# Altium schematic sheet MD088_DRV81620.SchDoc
size 431 x 279 mm; Date: Not shown in title block; ApprovedBy: Not shown in title block; CheckedBy: Not shown in title block; Author: Not shown in title block; CompanyName: Not shown in title block; Engineer: Not shown in title block; Organization: Not shown in title block; Address1: Not shown in title block; Address2: Not shown in title block; Address3: Not shown in title block; Address4: Not shown in title block; DocumentNumber: 1; Revision: Use project parameter SCH_Rev; SheetNumber: 1; SheetTotal: 4; PageSetup: Record=PageOptions¦CenterHorizontal=True¦CenterVertical=True¦PrintScale=1.00¦XCorrection=1.00¦YCorrection=1.00¦PrintKind=0¦BorderSize=5000000¦LeftOffset=0¦BottomOffset=0¦Orientation=2¦PaperLength=1000¦PaperWidth=1000¦Scale=100¦PaperSource=15¦PrintQuality=600¦MediaType=1¦DitherType=10¦PaperKind=Letter¦PrintScaleMode=1
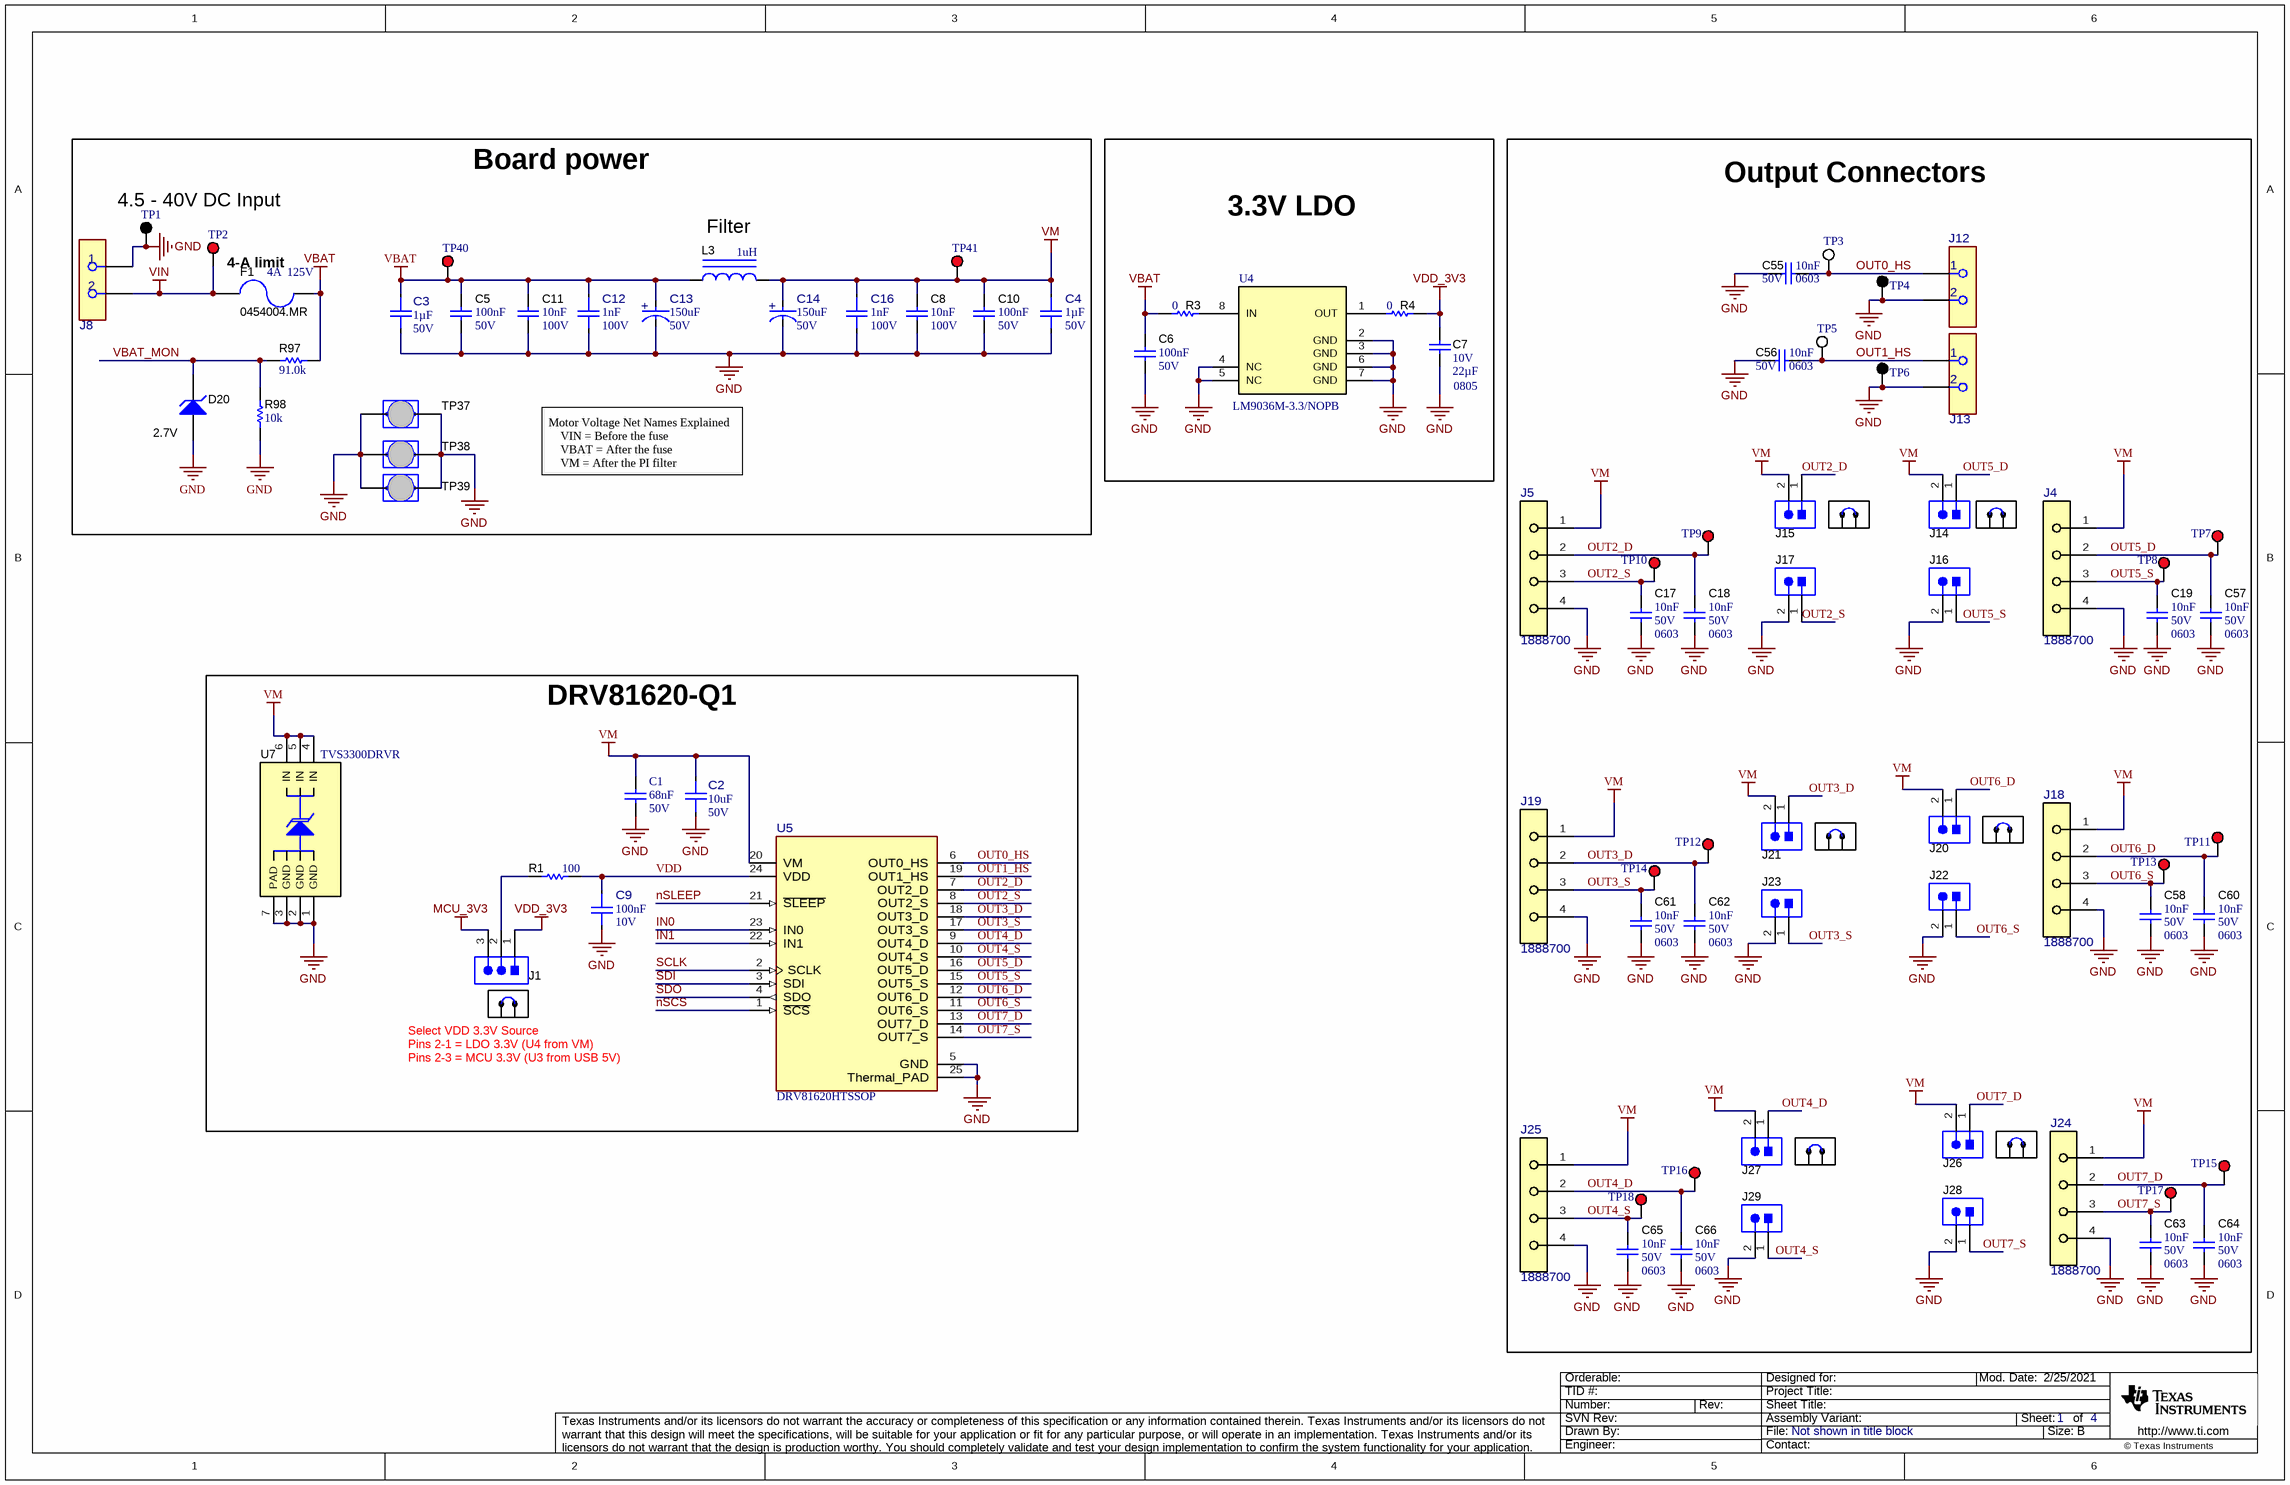
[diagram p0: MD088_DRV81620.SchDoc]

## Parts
C1  Cap_F: 68nF  Rated Voltage (DC): 50V  [WCAP-CSGP_0603_L1.6W0.8H0.8_Reflow]  (hidden comment: 885012206094)
C2  ValueDisplayed: 10uF  VDC_V: 50V  [FP-885012209073_1210-MFG]  (hidden comment: 885012209073)
C3  Cap_F: 1µF  VDC_V: 50V  [FP-885012206126_0603-MFG]  (hidden comment: 885012206126)
C4  Cap_F: 1µF  VDC_V: 50V  [FP-885012206126_0603-MFG]  (hidden comment: 885012206126)
C5  Cap_F: 100nF  VDC_V: 50V  [0603]  (hidden comment: 885012206095)
C6  Cap_F: 100nF  VDC_V: 50V  [0603]  (hidden comment: 885012206095)
C7  PackageReference: 0805  VDC_V: 10V  ValueDisplayed: 22µF  [0805_150]  (hidden comment: 885012107011)
C8  Value2: 100V  Cap_F: 10nF  [0603]  (hidden comment: 885012206114)
C9  value 100nF  VDC_V: 10V  [FP-885012205018_0402-MFG]  (hidden comment: 885012205018)
C10  Cap_F: 100nF  VDC_V: 50V  [0603]  (hidden comment: 885012206095)
C11  Value2: 100V  Cap_F: 10nF  [0603]  (hidden comment: 885012206114)
C12  ValueDisplayed: 1nF  VDC_V: 100V  [FP-885012006085_0603-MFG]  (hidden comment: 885012006085)
C13  VDC_V: 50V  ValueDisplayed: 150uF  [FP-865080657017_RADIAL-MFG]  (hidden comment: 865080657017)
C14  VDC_V: 50V  ValueDisplayed: 150uF  [FP-865080657017_RADIAL-MFG]  (hidden comment: 865080657017)
C16  ValueDisplayed: 1nF  VDC_V: 100V  [FP-885012006085_0603-MFG]  (hidden comment: 885012006085)
C17  VDC_V: 50V  Cap_F: 10nF  [0603]  (hidden comment: 885012206089)
C18  VDC_V: 50V  Cap_F: 10nF  [0603]  (hidden comment: 885012206089)
C19  VDC_V: 50V  Cap_F: 10nF  [0603]  (hidden comment: 885012206089)
C55  VDC_V: 50V  Cap_F: 10nF  [0603]  (hidden comment: 885012206089)
C56  VDC_V: 50V  Cap_F: 10nF  [0603]  (hidden comment: 885012206089)
C57  VDC_V: 50V  Cap_F: 10nF  [0603]  (hidden comment: 885012206089)
C58  VDC_V: 50V  Cap_F: 10nF  [0603]  (hidden comment: 885012206089)
C60  VDC_V: 50V  Cap_F: 10nF  [0603]  (hidden comment: 885012206089)
C61  VDC_V: 50V  Cap_F: 10nF  [0603]  (hidden comment: 885012206089)
C62  VDC_V: 50V  Cap_F: 10nF  [0603]  (hidden comment: 885012206089)
C63  VDC_V: 50V  Cap_F: 10nF  [0603]  (hidden comment: 885012206089)
C64  VDC_V: 50V  Cap_F: 10nF  [0603]  (hidden comment: 885012206089)
C65  VDC_V: 50V  Cap_F: 10nF  [0603]  (hidden comment: 885012206089)
C66  VDC_V: 50V  Cap_F: 10nF  [0603]  (hidden comment: 885012206089)
D20  value 2.7V  [SOD-123]  (hidden comment: MMSZ4682-E3-08)
F1  0454004.MR  Irating_A: 4A  VDC_V: 125V  [SloBlo452]
J1  61300311121  [WURTH_61300311121]  (value not drawn)
J4  1888700  [FP-1888700_HDR4-MFG]
J5  1888700  [FP-1888700_HDR4-MFG]
J8  691250610002  [FP-691250610002_CONN_TERM_BLOCK2-MFG]  (value not drawn)
J12  691101710002  [FP-691101710002_TERM_BLK_2-MFG]  (value not drawn)
J13  691101710002  [FP-691101710002_TERM_BLK_2-MFG]  (value not drawn)
J14  HTSW-102-07-G-S  [Samtec_HTSW-102-07-G-S]  (value not drawn)
J15  HTSW-102-07-G-S  [Samtec_HTSW-102-07-G-S]  (value not drawn)
J16  HTSW-102-07-G-S  [Samtec_HTSW-102-07-G-S]  (value not drawn)
J17  HTSW-102-07-G-S  [Samtec_HTSW-102-07-G-S]  (value not drawn)
J18  1888700  [FP-1888700_HDR4-MFG]
J19  1888700  [FP-1888700_HDR4-MFG]
J20  HTSW-102-07-G-S  [Samtec_HTSW-102-07-G-S]  (value not drawn)
J21  HTSW-102-07-G-S  [Samtec_HTSW-102-07-G-S]  (value not drawn)
J22  HTSW-102-07-G-S  [Samtec_HTSW-102-07-G-S]  (value not drawn)
J23  HTSW-102-07-G-S  [Samtec_HTSW-102-07-G-S]  (value not drawn)
J24  1888700  [FP-1888700_HDR4-MFG]
J25  1888700  [FP-1888700_HDR4-MFG]
J26  HTSW-102-07-G-S  [Samtec_HTSW-102-07-G-S]  (value not drawn)
J27  HTSW-102-07-G-S  [Samtec_HTSW-102-07-G-S]  (value not drawn)
J28  HTSW-102-07-G-S  [Samtec_HTSW-102-07-G-S]  (value not drawn)
J29  HTSW-102-07-G-S  [Samtec_HTSW-102-07-G-S]  (value not drawn)
L3  ValueDisplayed: 1uH  [WE-HCC_1210]  (hidden comment: 7443320100)
R1  ValueDisplayed: 100  [0402S]  (hidden comment: RC0402FR-07100RL)
R3  value 0  [0603L]  (hidden comment: Resistor)
R4  value 0  [0603L]  (hidden comment: Resistor)
R97  ValueDisplayed: 91.0k  [0603L]  (hidden comment: RG1608P-913-B-T5)
R98  ValueDisplayed: 10k  [0603L]  (hidden comment: RC0603JR-0710KL)
SH-J1  60900213421  [Wurth_60900213421]  (value not drawn)
SH-J23  60900213421  [Wurth_60900213421]  (value not drawn)
SH-J24  60900213421  [Wurth_60900213421]  (value not drawn)
SH-J25  60900213421  [Wurth_60900213421]  (value not drawn)
SH-J26  60900213421  [Wurth_60900213421]  (value not drawn)
SH-J29  60900213421  [Wurth_60900213421]  (value not drawn)
SH-J34  60900213421  [Wurth_60900213421]  (value not drawn)
TP1  5011  [Keystone5011]  (value not drawn)
TP2  5010  [Keystone5010]  (value not drawn)
TP3  5012  [Keystone5012]  (value not drawn)
TP4  5011  [Keystone5011]  (value not drawn)
TP5  5012  [Keystone5012]  (value not drawn)
TP6  5011  [Keystone5011]  (value not drawn)
TP7  5010  [Keystone5010]  (value not drawn)
TP8  5010  [Keystone5010]  (value not drawn)
TP9  5010  [Keystone5010]  (value not drawn)
TP10  5010  [Keystone5010]  (value not drawn)
TP11  5010  [Keystone5010]  (value not drawn)
TP12  5010  [Keystone5010]  (value not drawn)
TP13  5010  [Keystone5010]  (value not drawn)
TP14  5010  [Keystone5010]  (value not drawn)
TP15  5010  [Keystone5010]  (value not drawn)
TP16  5010  [Keystone5010]  (value not drawn)
TP17  5010  [Keystone5010]  (value not drawn)
TP18  5010  [Keystone5010]  (value not drawn)
TP37  Jumper_2p  [Harwin_D3082-05]  (value not drawn)
TP38  Jumper_2p  [Harwin_D3082-05]  (value not drawn)
TP39  Jumper_2p  [Harwin_D3082-05]  (value not drawn)
TP40  5010  [Keystone5010]  (value not drawn)
TP41  5010  [Keystone5010]  (value not drawn)
U4  LM9036M-3.3/NOPB  [D0008A_N]
U5  DRV81620HTSSOP  [PWP0024T-MFG]
U7  TVS3300DRVR  [DRV0006A]

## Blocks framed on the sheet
Board power: C3-C5 C8 C10-C14 C16 D20 F1 J8 L3 R97 R98 TP1 TP2 TP37-TP41
3.3V LDO: C6 C7 R3 R4 U4
Output Connectors: C17-C19 C55-C58 C60-C66 J4 J5 J12-J29 SH-J1 SH-J23-SH-J26 SH-J29 TP3-TP18
DRV81620-Q1: C1 C2 C9 J1 R1 SH-J34 U5 U7

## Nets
GND: C1.1 C2.1 C3.2 C4.2 C5.2 C6.2 C7.2 C8.1 C9.2 C10.2 C11.1 C12.2 C13.1(CATHODE) C14.1(CATHODE) C16.2 C17.2 C18.2 C19.2 C55.1 C56.1 C57.2 C58.2 C60.2 C61.2 C62.2 C63.2 C64.2 C65.2 C66.2 D20.2(A) J4.4 J5.4 J8.1 J12.2 J13.2 J16.2 J17.2 J18.4 J19.4 J22.2 J23.2 J24.4 J25.4 J28.2 J29.2 R98.2 TP1.1 TP4.1 TP6.1 TP37.1 TP37.2 TP38.1 TP38.2 TP39.1 TP39.2 U4.2(GND) U4.3(GND) U4.4(NC) U4.5(NC) U4.6(GND) U4.7(GND) U5.5(GND) U5.25(Thermal_PAD) U7.1(GND) U7.2(GND) U7.3(GND) U7.7(PAD)
MCU_3V3: J1.3
VBAT: C3.1 C5.1 C6.1 C11.2 C12.1 C13.2(ANODE) F1.1 L3.1 R3.2 R97.2 TP40.1
VDD_3V3: C7.1 J1.1 R4.1
VIN: F1.2 J8.2 TP2.1
VM: C1.2 C2.2 C4.1 C8.2 C10.1 C14.2(ANODE) C16.1 J4.1 J5.1 J14.2 J15.2 J18.1 J19.1 J20.2 J21.2 J24.1 J25.1 J26.2 J27.2 L3.2 TP41.1 U5.20(VM) U7.4(IN) U7.5(IN) U7.6(IN)
IN0: U5.23(IN0)
IN1: U5.22(IN1)
nSCS: U5.1(~{SCS})
nSLEEP: U5.21(~{SLEEP})
OUT0_HS: C55.2 J12.1 TP3.1 U5.6(OUT0_HS)
OUT1_HS: C56.2 J13.1 TP5.1 U5.19(OUT1_HS)
OUT2_D: C18.1 J5.2 J15.1 TP9.1 U5.7(OUT2_D)
OUT2_S: C17.1 J5.3 J17.1 TP10.1 U5.8(OUT2_S)
OUT3_D: C62.1 J19.2 J21.1 TP12.1 U5.18(OUT3_D)
OUT3_S: C61.1 J19.3 J23.1 TP14.1 U5.17(OUT3_S)
OUT4_D: C66.1 J25.2 J27.1 TP16.1 U5.9(OUT4_D)
OUT4_S: C65.1 J25.3 J29.1 TP18.1 U5.10(OUT4_S)
OUT5_D: C57.1 J4.2 J14.1 TP7.1 U5.16(OUT5_D)
OUT5_S: C19.1 J4.3 J16.1 TP8.1 U5.15(OUT5_S)
OUT6_D: C60.1 J18.2 J20.1 TP11.1 U5.12(OUT6_D)
OUT6_S: C58.1 J18.3 J22.1 TP13.1 U5.11(OUT6_S)
OUT7_D: C64.1 J24.2 J26.1 TP15.1 U5.13(OUT7_D)
OUT7_S: C63.1 J24.3 J28.1 TP17.1 U5.14(OUT7_S)
SCLK: U5.2(SCLK)
SDI: U5.3(SDI)
SDO: U5.4(SDO)
VBAT_MON: D20.1(K) R97.1 R98.1
VDD: C9.1 R1.1 U5.24(VDD)
NetJ1_2: J1.2 R1.2
NetR3_1: R3.1 U4.8(IN)
NetR4_2: R4.2 U4.1(OUT)

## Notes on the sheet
- (near TP1) 4.5 - 40V DC Input
- (near L3) Filter
- 4-A limit
- Motor Voltage Net Names Explained
  VIN = Before the fuse
  VBAT = After the fuse
  VM = After the PI filter
- (near SH-J34) Select VDD 3.3V Source
- (near SH-J34) Pins 2-3 = MCU 3.3V (U3 from USB 5V)
- (near SH-J34) Pins 2-1 = LDO 3.3V (U4 from VM)

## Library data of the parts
C1 = CMP-0111903-1: 68 nF ±10% 50V Ceramic Capacitor X7R 0603; Manufacturer: Wurth Elektronik; Capacitance Tolerance: +/-10%; Dissipation Factor: 3%; Insulation Resistance: 7.4GOhm; Match Code: WCAP-CSGP; Technical Reference: X7R0603683K050DFCT10000; Value: 68nF
C2 = CMP-0097489-1: 10 µF ±10% 50V Ceramic Capacitor X7R 1210 (3225 Metric); Manufacturer: Wurth Electronics; SizeZ_mm: 2.8mm; AEC Qualified: No; Value: 10µF; TempCo: 15%
C3 C4 = CMP-0120896-1: 1 µF ±10% 50V Ceramic Capacitor X7R 0603 (1608 Metric); Manufacturer: Wurth Electronics; AEC Qualified: No; SizeZ_mm: 0.95mm; TempCo: 15%; ValueDisplayed: 1uF; Value: 1µF
C5 C6 C10 = CMP-0006837-4: CAP, CERM, 0.1 uF, 50 V, +/- 10%, X7R, 0603; Manufacturer: Wurth Elektronik; TaMin_C: -55°C; Polarized: N; SizeAreaWB_mm2: 4.68; Value1: Unknown; U/M: EA; Value: 0.1uF; TaMax_C: 125°C; SizeZ_mm: 1; SizeX_mm: 1.6; SizeY_mm: 0.8; SizeArea_mm2: 1.28; AEC Category: Q200
C7 = CMP-0078153-1: CAP, CERM, 22 µF, 10 V,+/- 20%, X5R, 0805; Manufacturer: Wurth Elektronik; TaMin_C: -55°C; Polarized: N; SizeAreaWB_mm2: 6.75; U/M: EA; Value: 22uF; TaMax_C: 85°C; SizeZ_mm: 1.5; SizeX_mm: 2; SizeY_mm: 1.25; SizeArea_mm2: 2.5; AEC Category: Q200
C8 C11 = CMP-0079993-1: CAP, CERM, 0.01 µF, 100 V,+/- 10%, X7R, 0603; Manufacturer: Wurth Elektronik; TaMin_C: -55°C; Polarized: N; SizeAreaWB_mm2: 4.68; U/M: EA; Value: 0.01uF; TaMax_C: 105°C; SizeZ_mm: 1; SizeX_mm: 1.6; SizeY_mm: 0.8; SizeArea_mm2: 1.28; AEC Category: Q200; ValueDisplayed: 0.01µF
C9 = CMP-0090362-1: 0.1µF ±10% 10V Ceramic Capacitor X7R 0402 (1005 Metric); Manufacturer: Wurth Electronics; AEC Qualified: No; SizeZ_mm: 0.55mm; ValueDisplayed: 100000pF; TempCo: 15%
C12 C16 = CMP-0097311-1: 1000 pF ±5% 100V Ceramic Capacitor C0G, NP0 0603 (1608 Metric); Manufacturer: Wurth Electronics; TempCo: 30ppm/°C; SizeZ_mm: 0.87mm; AEC Qualified: No; Value: 1nF
C13 C14 = CMP-0097488-1: 150 µF 50 V Aluminum Electrolytic Capacitors Radial, Can - SMD 2000 Hrs @ 105°C; Manufacturer: Wurth Electronics; Cap_F: 150µF; Life: 2000Hours; IRMS_A: 600mA; Dissipation Factor: 12%; Value: 150µF; Leakage Current: 75uA; Tolerance_%: 20%; AEC Qualified: No; SizeZ_mm: 10.5mm
C17-C19 C55-C58 C60-C66 = CMP-0750039-1: CAP, CERM, 0.01 µF, 50 V,+/- 10%, X7R, 0603; Manufacturer: Wurth Elektronik; Polarized: N; AEC Category: Q200; TaMax_C: 125°C; SizeAreaWB_mm2: 4.68; Value: 0.01uF; SizeArea_mm2: 1.28; SizeY_mm: 0.8; SizeZ_mm: 1; ValueDisplayed: 0.01µF; SizeX_mm: 1.6; U/M: EA; TaMin_C: -55°C
D20 = CMP-0077592-3: Diode, Zener, 2.7 V, 500 mW, SOD-123; Manufacturer: Vishay-Semiconductor; AEC Category: Q101; AEC Qualified: N; SizeAreaWB_mm2: 13.095; SizeY_mm: 1.7; SizeX_mm: 3.85; Value1: 0.5W; SizeArea_mm2: 6.545; SizeZ_mm: 1.35; RJA_CperW: 340; Power_W: 500mW
F1 = CMP-0003486-2: Fuse, 4 A, 125VAC/VDC, SMD; Manufacturer: Littelfuse; MeltingTyp: 34.4; Rtyp_Ohm: 0.0186; Interrupt_AC: 50A; Value: 4A / 125V
J1 = CMP-0054796-4: Header, 2.54 mm, 3x1, Gold, TH; Manufacturer: Wurth Elektronik; Green_Lifecycle: Active; Green_REACh: Passed; CT: FALSE; CNHeader: TRUE
J4 J5 J18 J19 J24 J25 = CMP-0086377-1: Conn; Term Blk; PCB; Screw; 4; 5.08 mm; Front; 24-14 AWG; 16 A; 250 V; Solder; Manufacturer: Phoenix Contact; ContactFinish: Tin; Current_A: 16A; Row_Count: 1; Voltage_V: 400V
J8 = CMP-0093233-2: 2 Position Wire to Board Terminal Block Horizontal with Board 0.250" (6.35mm) Through Hole; Manufacturer: Wurth Electronics; Current_A: 32A; Conn Gender: Female; Row_Count: 1; ContactFinish: Zinc; SizeZ_mm: 21.6mm; Max Wire Gauge: 10; Min Wire Gauge: 30; Voltage_V: 450V; AEC Qualified: No; Is Female: yes
J12 J13 = CMP-0121353-1: 2 Position Wire to Board Terminal Block Horizontal with Board 0.197" (5.00mm) Through Hole; Manufacturer: Wurth; Current_A: 16A; Row_Count: 1; Voltage_V: 250V; AEC Qualified: No; Conn Gender: Female; DUT-Pitch_mm: 5mm; Is Female: yes; Max Wire Gauge: 14; Min Wire Gauge: 26; SizeZ_mm: 12.8mm
J14-J17 J20-J23 J26-J29 = CMP-0075483-1: Header, 100mil, 2x1, Gold, TH; Manufacturer: Samtec; Green_REACh: Passed; CT: False; Green_Lifecycle: Active; CNHeader: True
L3 = CMP-0063986-1: Inductor, Shielded Drum Core, Ferrite, 1 uH, 24 A, 0.0012 ohm, SMD; Manufacturer: Wurth Elektronik; Isat: 32A @ 30% inductance drop; Irms: 24A @ 50C rise; Green_Lifecycle: Active; SizeAreaWB_mm2: 188.94; DCR_ohm: 1.2m; Green_REACh: Passed; Value: 1uH; Imax_A: 24A; SizeZ_mm: 10; SizeX_mm: 12.1; SizeY_mm: 11.4; SizeArea_mm2: 137.94; Ind_H: 1µH; AEC Category: Q200
R1 = CMP-0026722-1: RES, 100, 1%, 0.063 W, 0402; Manufacturer: Yageo America; Power_W: 63mW; TempCo: 100 ppm/C; Value_Code: 100R; U/M: EA; Value: 100; EIA_Code: E96; SizeX_mm: 1; SizeY_mm: 0.5; SizeZ_mm: 0.6; Value2: 0.063W; AEC Qualified: N; VDC_V: 50V; AEC Category: Q200
R3 R4 = CMP-0025697-4: RES, 0, 5%, 0.1 W, AEC-Q200 Grade 0, 0603; PartNumber: CRCW06030000Z0EA; Manufacturer: Vishay-Dale; Value_Code: 0000; Power_W: 100mW; Value2: 0.1W; VDC_V: 75V; TempCo: 200 ppm/C; EIA_Code: E24; AEC Category: Q200; AEC Qualified: Y; SizeArea_mm2: 1.28; SizeX_mm: 1.6; SizeY_mm: 0.8; SizeZ_mm: 1
R97 = CMP-0023620-3: RES, 91.0 k, 0.1%, 0.1 W, 0603; Manufacturer: Susumu Co Ltd; Power_W: 100mW; TempCo: 25 ppm/C; Value_Code: 91k0; U/M: EA; Value: 91.0k; Res_ohm: 91k; SizeX_mm: 1.6; SizeY_mm: 0.8; SizeZ_mm: 1; Value2: 0.1W; SizeArea_mm2: 1.28; VDC_V: 75V; AEC Category: Q200
R98 = CMP-0025886-5: RES, 10 k, 5%, 0.1 W, 0603; Manufacturer: Yageo; Power_W: 100mW; TempCo: 100 ppm/C; Value_Code: 10k0; Value: 10k; EIA_Code: E24; SizeX_mm: 1.6; SizeY_mm: 0.8; SizeZ_mm: 1; Value2: 0.1W; SizeArea_mm2: 1.28; AEC Qualified: N; VDC_V: 75V; AEC Category: Q200; SizeAreaWB_mm2: 4.68
SH-J1 SH-J23-SH-J26 SH-J29 SH-J34 = CMP-0003761-2: Shunt, 2.54mm, Gold, Black; Manufacturer: Wurth Elektronik
TP1 TP4 TP6 = CMP-0055148-2: Test Point, Multipurpose, Black, TH; Manufacturer: Keystone Electronics; CNHeader: FALSE; Green_Lifecycle: Active; Green_REACh: Passed; ContactFinish: Silver; CT: TRUE
TP2 TP7-TP18 TP40 TP41 = CMP-0055147-2: Test Point, Multipurpose, Red, TH; Manufacturer: Keystone Electronics; CNHeader: FALSE; Green_Lifecycle: Active; Green_REACh: Passed; ContactFinish: Silver; CT: TRUE
TP3 TP5 = CMP-0055149-2: Test Point, Multipurpose, White, TH; Manufacturer: Keystone Electronics; ContactFinish: Silver; CT: TRUE; CNHeader: FALSE; Green_Lifecycle: Active; Green_REACh: Passed
TP37-TP39 = CMP-0075110-1: 1mm Uninsulated Shorting Plug, 10.16mm spacing, TH; Manufacturer: Harwin; PartNumber: D3082-05; CompType: Jumper Wire; CNHeader: False; Green_Lifecycle: Active; Green_REACh: Passed
U4 = CMP-0070570-1: Ultra-Low Quiescent Current Voltage Regulator, 8-pin Narrow SOIC, Pb-Free; Manufacturer: Texas Instruments; PackageTopMarking: NSZXTT*LM903*6M-3; PowerWise: N; CompType: LDO IC
U5 = CMP-0120421-1: 8-channel Configurable Low-side and High-side Driver for Automotive Relay, Lighting and Motor Control; Manufacturer: Texas Instruments; SizeZ_mm: 1.2mm; AEC Qualified: No; Max Supply Voltage: 40V; Min Supply Voltage: 3V; Number Of Outputs: 8; Standoff Height: 0.05mm; TaMax_C: +125°C; TaMin_C: -40°C; TJmax_C: +150°C
U7 = CMP-0013424-7: 33-V Precision Surge Protection Clamp, DRV0006A (WSON-6); Manufacturer: Texas Instruments; SizeX_mm: 2; CompType: IC; SizeZ_mm: 0.8; SizeArea_mm2: 4; SizeAreaWB_mm2: 9; U/M: EA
